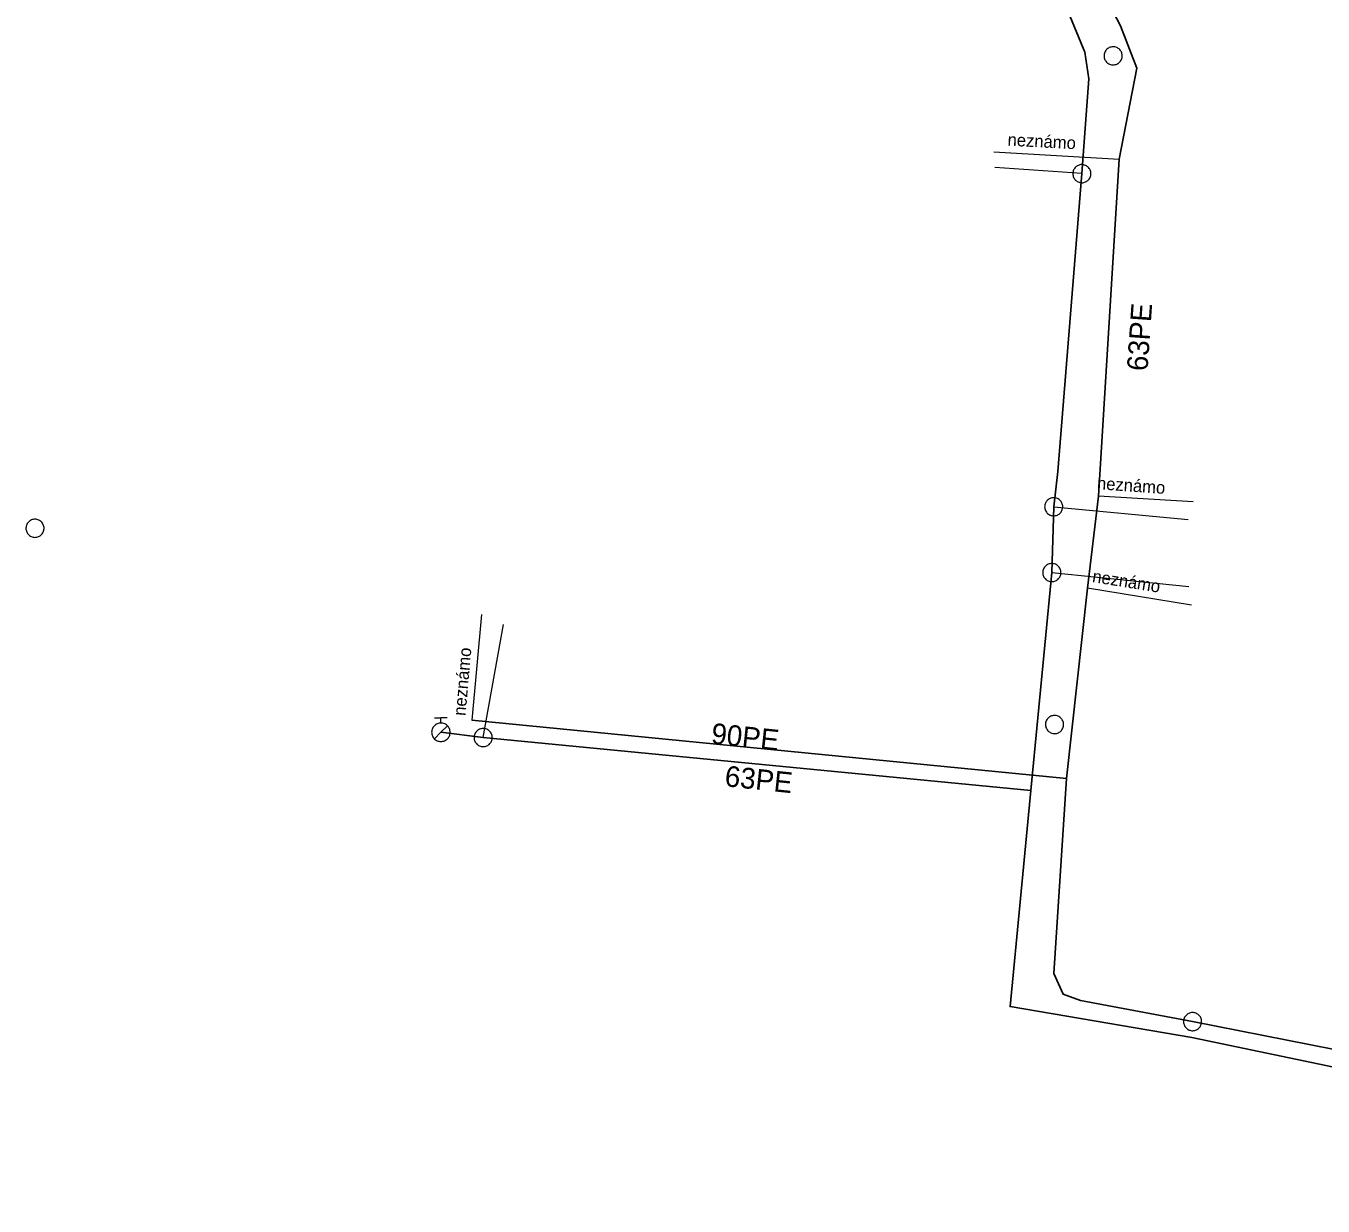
# Model space of a CAD drawing. Extents: x -741806 to -738704, y -1059275 to -1055387.
# Drawn here: x -740718.4 to -740655.8, y -1057566.4 to -1057509.4 of the extents above; entities that cross this region are included whole.
import ezdxf

# ---------------------------------------------------------------- set-up
doc = ezdxf.new("R2010")
doc.units = 0
doc.header["$LTSCALE"] = 0.4
for name, color, linetype, lineweight in [('2', 7, 'Continuous', 25), ('21', 7, 'Continuous', 13), ('3', 7, 'Continuous', 13), ('50', 7, 'Continuous', 13), ('51', 7, 'Continuous', 13), ('52', 7, 'Continuous', 25), ('56', 7, 'Continuous', 13)]:
    doc.layers.add(name, color=color, linetype=linetype, lineweight=lineweight)
for name, color, linetype in [('5', 7, 'Continuous'), ('53', 7, 'Continuous'), ('55', 7, 'Continuous')]:
    doc.layers.add(name, color=color, linetype=linetype)

msp = doc.modelspace()

# ---------------------------------------------------------------- linework, layer by layer
at = {"layer": '2'}
msp.add_line((-740696.899, -1057542.97), (-740668.18, -1057545.78), dxfattribs=at)
msp.add_lwpolyline([(-740701.18, -1057473.159), (-740698.129, -1057473.58), (-740689.684, -1057473.824), (-740686.82, -1057473.879), (-740685.879, -1057474.169), (-740685.34, -1057475.12), (-740682.62, -1057479.69), (-740667.039, -1057506.61), (-740665.579, -1057509.429), (-740664.78, -1057511.48), (-740665.629, -1057515.87), (-740666.629, -1057532.149), (-740667.16, -1057536.6), (-740668.18, -1057545.78), (-740668.8, -1057555.2), (-740668.35, -1057556.21), (-740667.51, -1057556.51), (-740662.09, -1057557.53), (-740650.66, -1057559.78), (-740647.78, -1057560.7), (-740633.18, -1057564.139), (-740633.142, -1057565.869)], dxfattribs=at)
at = {"layer": '21'}
for p, q in [((-740667.44, -1057516.57), (-740671.64, -1057516.27)), ((-740668.8, -1057532.659), (-740662.309, -1057533.27)), ((-740668.89, -1057535.84), (-740662.27, -1057536.51)), ((-740696.359, -1057543.81), (-740695.379, -1057538.35))]:
    msp.add_line(p, q, dxfattribs=at)
at = {"layer": '3'}
for points in [[(-740665.891, -1057510.442), (-740665.936, -1057510.441), (-740665.981, -1057510.444), (-740666.027, -1057510.452), (-740666.07, -1057510.465), (-740666.113, -1057510.482), (-740666.154, -1057510.503), (-740666.192, -1057510.529), (-740666.227, -1057510.558), (-740666.258, -1057510.592), (-740666.286, -1057510.627), (-740666.311, -1057510.666), (-740666.332, -1057510.708), (-740666.346, -1057510.751), (-740666.358, -1057510.795), (-740666.364, -1057510.84), (-740666.366, -1057510.886), (-740666.362, -1057510.932), (-740666.355, -1057510.977), (-740666.342, -1057511.021), (-740666.325, -1057511.064), (-740666.303, -1057511.104), (-740666.278, -1057511.141), (-740666.248, -1057511.177), (-740666.216, -1057511.209), (-740666.179, -1057511.237), (-740666.14, -1057511.261), (-740666.1, -1057511.281), (-740666.056, -1057511.297), (-740666.012, -1057511.308), (-740665.966, -1057511.314), (-740665.921, -1057511.316), (-740665.876, -1057511.313), (-740665.83, -1057511.305), (-740665.786, -1057511.292), (-740665.744, -1057511.275), (-740665.703, -1057511.254), (-740665.665, -1057511.228), (-740665.63, -1057511.198), (-740665.599, -1057511.165), (-740665.571, -1057511.13), (-740665.546, -1057511.091), (-740665.525, -1057511.049), (-740665.51, -1057511.007), (-740665.499, -1057510.962), (-740665.493, -1057510.917), (-740665.491, -1057510.871), (-740665.494, -1057510.825), (-740665.502, -1057510.78), (-740665.515, -1057510.736), (-740665.532, -1057510.693), (-740665.554, -1057510.653), (-740665.579, -1057510.615), (-740665.609, -1057510.58), (-740665.641, -1057510.548), (-740665.678, -1057510.52), (-740665.717, -1057510.496), (-740665.757, -1057510.476), (-740665.801, -1057510.46), (-740665.845, -1057510.449), (-740665.89, -1057510.442)], [(-740717.958, -1057533.265), (-740718.003, -1057533.262), (-740718.048, -1057533.264), (-740718.094, -1057533.271), (-740718.138, -1057533.282), (-740718.181, -1057533.298), (-740718.223, -1057533.318), (-740718.261, -1057533.343), (-740718.297, -1057533.37), (-740718.329, -1057533.403), (-740718.359, -1057533.438), (-740718.384, -1057533.476), (-740718.406, -1057533.517), (-740718.422, -1057533.559), (-740718.436, -1057533.603), (-740718.443, -1057533.648), (-740718.446, -1057533.694), (-740718.444, -1057533.74), (-740718.438, -1057533.785), (-740718.426, -1057533.83), (-740718.41, -1057533.873), (-740718.39, -1057533.913), (-740718.366, -1057533.951), (-740718.337, -1057533.988), (-740718.306, -1057534.021), (-740718.27, -1057534.05), (-740718.232, -1057534.075), (-740718.192, -1057534.097), (-740718.149, -1057534.114), (-740718.105, -1057534.126), (-740718.059, -1057534.134), (-740718.014, -1057534.137), (-740717.969, -1057534.135), (-740717.923, -1057534.129), (-740717.878, -1057534.117), (-740717.836, -1057534.102), (-740717.794, -1057534.081), (-740717.756, -1057534.057), (-740717.719, -1057534.028), (-740717.688, -1057533.996), (-740717.658, -1057533.961), (-740717.633, -1057533.923), (-740717.611, -1057533.883), (-740717.594, -1057533.84), (-740717.581, -1057533.796), (-740717.574, -1057533.751), (-740717.571, -1057533.705), (-740717.572, -1057533.659), (-740717.579, -1057533.614), (-740717.591, -1057533.57), (-740717.607, -1057533.526), (-740717.627, -1057533.486), (-740717.651, -1057533.447), (-740717.68, -1057533.411), (-740717.711, -1057533.378), (-740717.747, -1057533.349), (-740717.785, -1057533.323), (-740717.825, -1057533.302), (-740717.868, -1057533.285), (-740717.912, -1057533.273), (-740717.957, -1057533.265)], [(-740668.721, -1057542.742), (-740668.766, -1057542.741), (-740668.811, -1057542.744), (-740668.857, -1057542.752), (-740668.9, -1057542.765), (-740668.943, -1057542.782), (-740668.984, -1057542.803), (-740669.022, -1057542.829), (-740669.057, -1057542.858), (-740669.088, -1057542.892), (-740669.116, -1057542.927), (-740669.141, -1057542.966), (-740669.162, -1057543.008), (-740669.176, -1057543.051), (-740669.188, -1057543.095), (-740669.194, -1057543.14), (-740669.196, -1057543.186), (-740669.192, -1057543.232), (-740669.185, -1057543.277), (-740669.172, -1057543.321), (-740669.155, -1057543.364), (-740669.133, -1057543.404), (-740669.108, -1057543.441), (-740669.078, -1057543.477), (-740669.046, -1057543.509), (-740669.009, -1057543.537), (-740668.97, -1057543.561), (-740668.93, -1057543.581), (-740668.886, -1057543.597), (-740668.842, -1057543.608), (-740668.796, -1057543.614), (-740668.751, -1057543.616), (-740668.706, -1057543.613), (-740668.66, -1057543.605), (-740668.616, -1057543.592), (-740668.574, -1057543.575), (-740668.533, -1057543.554), (-740668.495, -1057543.528), (-740668.46, -1057543.498), (-740668.429, -1057543.465), (-740668.401, -1057543.43), (-740668.376, -1057543.391), (-740668.355, -1057543.349), (-740668.34, -1057543.307), (-740668.329, -1057543.262), (-740668.323, -1057543.217), (-740668.321, -1057543.171), (-740668.324, -1057543.125), (-740668.332, -1057543.08), (-740668.345, -1057543.036), (-740668.362, -1057542.993), (-740668.384, -1057542.953), (-740668.409, -1057542.915), (-740668.439, -1057542.88), (-740668.471, -1057542.848), (-740668.508, -1057542.82), (-740668.547, -1057542.796), (-740668.587, -1057542.776), (-740668.631, -1057542.76), (-740668.675, -1057542.749), (-740668.72, -1057542.742)], [(-740661.659, -1057557.611), (-740661.654, -1057557.566), (-740661.652, -1057557.521), (-740661.656, -1057557.474), (-740661.664, -1057557.43), (-740661.677, -1057557.386), (-740661.694, -1057557.343), (-740661.716, -1057557.303), (-740661.742, -1057557.265), (-740661.772, -1057557.231), (-740661.804, -1057557.199), (-740661.841, -1057557.171), (-740661.88, -1057557.146), (-740661.921, -1057557.127), (-740661.964, -1057557.111), (-740662.009, -1057557.101), (-740662.054, -1057557.094), (-740662.1, -1057557.094), (-740662.145, -1057557.096), (-740662.191, -1057557.105), (-740662.235, -1057557.118), (-740662.277, -1057557.136), (-740662.316, -1057557.157), (-740662.355, -1057557.183), (-740662.39, -1057557.212), (-740662.422, -1057557.246), (-740662.449, -1057557.282), (-740662.473, -1057557.32), (-740662.494, -1057557.362), (-740662.509, -1057557.405), (-740662.519, -1057557.45), (-740662.526, -1057557.495), (-740662.527, -1057557.54), (-740662.524, -1057557.587), (-740662.515, -1057557.632), (-740662.503, -1057557.675), (-740662.485, -1057557.718), (-740662.463, -1057557.758), (-740662.437, -1057557.796), (-740662.408, -1057557.83), (-740662.375, -1057557.862), (-740662.338, -1057557.89), (-740662.299, -1057557.915), (-740662.258, -1057557.935), (-740662.215, -1057557.95), (-740662.171, -1057557.96), (-740662.125, -1057557.967), (-740662.08, -1057557.968), (-740662.034, -1057557.965), (-740661.989, -1057557.956), (-740661.944, -1057557.943), (-740661.902, -1057557.925), (-740661.862, -1057557.905), (-740661.824, -1057557.878), (-740661.789, -1057557.849), (-740661.758, -1057557.815), (-740661.729, -1057557.779), (-740661.706, -1057557.741), (-740661.686, -1057557.699), (-740661.671, -1057557.656), (-740661.659, -1057557.612)]]:
    msp.add_lwpolyline(points, dxfattribs=at)
at = {"layer": '50'}
for p, q in [((-740698.707, -1057542.856), (-740698.399, -1057542.856)), ((-740698.399, -1057543.107), (-740698.399, -1057542.856)), ((-740698.092, -1057542.856), (-740698.399, -1057542.856)), ((-740698.399, -1057543.554), (-740698.083, -1057543.242)), ((-740698.399, -1057543.554), (-740698.716, -1057543.871))]:
    msp.add_line(p, q, dxfattribs=at)
msp.add_lwpolyline([(-740697.955, -1057543.558), (-740697.957, -1057543.509), (-740697.962, -1057543.463), (-740697.975, -1057543.417), (-740697.992, -1057543.374), (-740698.011, -1057543.334), (-740698.038, -1057543.293), (-740698.067, -1057543.258), (-740698.1, -1057543.223), (-740698.135, -1057543.193), (-740698.175, -1057543.169), (-740698.216, -1057543.147), (-740698.259, -1057543.128), (-740698.305, -1057543.118), (-740698.351, -1057543.11), (-740698.397, -1057543.107), (-740698.443, -1057543.11), (-740698.488, -1057543.115), (-740698.534, -1057543.128), (-740698.578, -1057543.145), (-740698.621, -1057543.166), (-740698.659, -1057543.191), (-740698.696, -1057543.22), (-740698.729, -1057543.253), (-740698.758, -1057543.288), (-740698.785, -1057543.328), (-740698.807, -1057543.369), (-740698.823, -1057543.412), (-740698.837, -1057543.458), (-740698.842, -1057543.504), (-740698.848, -1057543.55), (-740698.846, -1057543.598), (-740698.838, -1057543.644), (-740698.827, -1057543.687), (-740698.811, -1057543.733), (-740698.789, -1057543.774), (-740698.765, -1057543.814), (-740698.735, -1057543.849), (-740698.703, -1057543.884), (-740698.665, -1057543.914), (-740698.627, -1057543.938), (-740698.584, -1057543.96), (-740698.541, -1057543.976), (-740698.498, -1057543.99), (-740698.449, -1057543.998), (-740698.403, -1057544.001), (-740698.357, -1057543.998), (-740698.311, -1057543.99), (-740698.265, -1057543.979), (-740698.222, -1057543.963), (-740698.179, -1057543.941), (-740698.141, -1057543.917), (-740698.103, -1057543.887), (-740698.071, -1057543.855), (-740698.041, -1057543.82), (-740698.017, -1057543.779), (-740697.993, -1057543.739), (-740697.976, -1057543.695), (-740697.966, -1057543.65), (-740697.958, -1057543.604)], close=True, dxfattribs=at)
at = {"layer": '51'}
for points in [[(-740667.002, -1057516.57), (-740667.004, -1057516.525), (-740667.012, -1057516.48), (-740667.024, -1057516.435), (-740667.039, -1057516.393), (-740667.061, -1057516.352), (-740667.085, -1057516.313), (-740667.115, -1057516.278), (-740667.147, -1057516.245), (-740667.183, -1057516.217), (-740667.22, -1057516.192), (-740667.262, -1057516.171), (-740667.304, -1057516.154), (-740667.348, -1057516.142), (-740667.394, -1057516.135), (-740667.44, -1057516.133), (-740667.485, -1057516.135), (-740667.531, -1057516.142), (-740667.575, -1057516.154), (-740667.617, -1057516.171), (-740667.659, -1057516.192), (-740667.696, -1057516.217), (-740667.732, -1057516.245), (-740667.764, -1057516.278), (-740667.794, -1057516.313), (-740667.818, -1057516.352), (-740667.84, -1057516.393), (-740667.855, -1057516.435), (-740667.867, -1057516.48), (-740667.875, -1057516.525), (-740667.877, -1057516.571), (-740667.875, -1057516.616), (-740667.867, -1057516.661), (-740667.855, -1057516.706), (-740667.84, -1057516.748), (-740667.818, -1057516.789), (-740667.794, -1057516.828), (-740667.764, -1057516.863), (-740667.732, -1057516.896), (-740667.696, -1057516.924), (-740667.659, -1057516.949), (-740667.617, -1057516.97), (-740667.575, -1057516.987), (-740667.531, -1057516.998), (-740667.485, -1057517.006), (-740667.44, -1057517.008), (-740667.394, -1057517.006), (-740667.348, -1057516.998), (-740667.304, -1057516.987), (-740667.262, -1057516.97), (-740667.22, -1057516.949), (-740667.183, -1057516.924), (-740667.147, -1057516.896), (-740667.115, -1057516.863), (-740667.085, -1057516.828), (-740667.061, -1057516.789), (-740667.039, -1057516.748), (-740667.024, -1057516.706), (-740667.012, -1057516.661), (-740667.004, -1057516.616), (-740667.002, -1057516.571)], [(-740668.363, -1057532.659), (-740668.365, -1057532.614), (-740668.372, -1057532.569), (-740668.384, -1057532.524), (-740668.4, -1057532.482), (-740668.421, -1057532.441), (-740668.446, -1057532.402), (-740668.475, -1057532.367), (-740668.507, -1057532.334), (-740668.543, -1057532.306), (-740668.581, -1057532.281), (-740668.622, -1057532.26), (-740668.665, -1057532.243), (-740668.709, -1057532.231), (-740668.754, -1057532.224), (-740668.8, -1057532.222), (-740668.846, -1057532.224), (-740668.891, -1057532.231), (-740668.935, -1057532.243), (-740668.978, -1057532.26), (-740669.019, -1057532.281), (-740669.057, -1057532.306), (-740669.093, -1057532.334), (-740669.125, -1057532.367), (-740669.154, -1057532.402), (-740669.179, -1057532.441), (-740669.2, -1057532.482), (-740669.216, -1057532.524), (-740669.228, -1057532.569), (-740669.235, -1057532.614), (-740669.238, -1057532.66), (-740669.235, -1057532.705), (-740669.228, -1057532.75), (-740669.216, -1057532.795), (-740669.2, -1057532.837), (-740669.179, -1057532.878), (-740669.154, -1057532.917), (-740669.125, -1057532.952), (-740669.093, -1057532.985), (-740669.057, -1057533.013), (-740669.019, -1057533.038), (-740668.978, -1057533.059), (-740668.935, -1057533.076), (-740668.891, -1057533.087), (-740668.846, -1057533.095), (-740668.8, -1057533.097), (-740668.754, -1057533.095), (-740668.709, -1057533.087), (-740668.665, -1057533.076), (-740668.622, -1057533.059), (-740668.581, -1057533.038), (-740668.543, -1057533.013), (-740668.507, -1057532.985), (-740668.475, -1057532.952), (-740668.446, -1057532.917), (-740668.421, -1057532.878), (-740668.4, -1057532.837), (-740668.384, -1057532.795), (-740668.372, -1057532.75), (-740668.365, -1057532.705), (-740668.363, -1057532.66)], [(-740668.453, -1057535.84), (-740668.455, -1057535.795), (-740668.462, -1057535.75), (-740668.474, -1057535.705), (-740668.49, -1057535.663), (-740668.511, -1057535.622), (-740668.536, -1057535.583), (-740668.565, -1057535.548), (-740668.597, -1057535.515), (-740668.633, -1057535.487), (-740668.671, -1057535.462), (-740668.712, -1057535.441), (-740668.755, -1057535.424), (-740668.799, -1057535.412), (-740668.844, -1057535.405), (-740668.89, -1057535.403), (-740668.936, -1057535.405), (-740668.981, -1057535.412), (-740669.025, -1057535.424), (-740669.068, -1057535.441), (-740669.109, -1057535.462), (-740669.147, -1057535.487), (-740669.183, -1057535.515), (-740669.215, -1057535.548), (-740669.244, -1057535.583), (-740669.269, -1057535.622), (-740669.29, -1057535.663), (-740669.306, -1057535.705), (-740669.318, -1057535.75), (-740669.325, -1057535.795), (-740669.328, -1057535.841), (-740669.325, -1057535.886), (-740669.318, -1057535.931), (-740669.306, -1057535.976), (-740669.29, -1057536.018), (-740669.269, -1057536.059), (-740669.244, -1057536.098), (-740669.215, -1057536.133), (-740669.183, -1057536.166), (-740669.147, -1057536.194), (-740669.109, -1057536.219), (-740669.068, -1057536.24), (-740669.025, -1057536.257), (-740668.981, -1057536.268), (-740668.936, -1057536.276), (-740668.89, -1057536.278), (-740668.844, -1057536.276), (-740668.799, -1057536.268), (-740668.755, -1057536.257), (-740668.712, -1057536.24), (-740668.671, -1057536.219), (-740668.633, -1057536.194), (-740668.597, -1057536.166), (-740668.565, -1057536.133), (-740668.536, -1057536.098), (-740668.511, -1057536.059), (-740668.49, -1057536.018), (-740668.474, -1057535.976), (-740668.462, -1057535.931), (-740668.455, -1057535.886), (-740668.453, -1057535.841)], [(-740695.922, -1057543.81), (-740695.924, -1057543.765), (-740695.931, -1057543.72), (-740695.943, -1057543.675), (-740695.959, -1057543.633), (-740695.98, -1057543.592), (-740696.005, -1057543.553), (-740696.034, -1057543.518), (-740696.066, -1057543.485), (-740696.102, -1057543.457), (-740696.14, -1057543.432), (-740696.181, -1057543.411), (-740696.224, -1057543.394), (-740696.268, -1057543.382), (-740696.313, -1057543.375), (-740696.359, -1057543.373), (-740696.405, -1057543.375), (-740696.45, -1057543.382), (-740696.494, -1057543.394), (-740696.537, -1057543.411), (-740696.578, -1057543.432), (-740696.616, -1057543.457), (-740696.652, -1057543.485), (-740696.684, -1057543.518), (-740696.713, -1057543.553), (-740696.738, -1057543.592), (-740696.759, -1057543.633), (-740696.775, -1057543.675), (-740696.787, -1057543.72), (-740696.794, -1057543.765), (-740696.797, -1057543.811), (-740696.794, -1057543.856), (-740696.787, -1057543.901), (-740696.775, -1057543.946), (-740696.759, -1057543.988), (-740696.738, -1057544.029), (-740696.713, -1057544.068), (-740696.684, -1057544.103), (-740696.652, -1057544.136), (-740696.616, -1057544.164), (-740696.578, -1057544.189), (-740696.537, -1057544.21), (-740696.494, -1057544.227), (-740696.45, -1057544.238), (-740696.405, -1057544.246), (-740696.359, -1057544.248), (-740696.313, -1057544.246), (-740696.268, -1057544.238), (-740696.224, -1057544.227), (-740696.181, -1057544.21), (-740696.14, -1057544.189), (-740696.102, -1057544.164), (-740696.066, -1057544.136), (-740696.034, -1057544.103), (-740696.005, -1057544.068), (-740695.98, -1057544.029), (-740695.959, -1057543.988), (-740695.943, -1057543.946), (-740695.931, -1057543.901), (-740695.924, -1057543.856), (-740695.922, -1057543.811)]]:
    msp.add_lwpolyline(points, dxfattribs=at)
at = {"layer": '52'}
for points in [[(-740669.903, -1057546.362), (-740668.89, -1057535.84), (-740668.8, -1057532.659), (-740668.6, -1057530.96), (-740667.44, -1057516.57), (-740667.109, -1057511.99), (-740667.289, -1057510.7), (-740668.399, -1057507.99), (-740683.739, -1057481.02), (-740686.96, -1057476.45), (-740689.02, -1057475.889), (-740697.39, -1057475.629), (-740700.809, -1057475.34), (-740703.14, -1057474.73)], [(-740669.903, -1057546.362), (-740696.359, -1057543.81), (-740698.399, -1057543.55)], [(-740622.261, -1057566.439), (-740622.739, -1057566.399), (-740633.96, -1057565.02), (-740651.25, -1057560.57), (-740662.129, -1057558.3), (-740670.91, -1057556.8), (-740669.903, -1057546.362)]]:
    msp.add_lwpolyline(points, dxfattribs=at)
at = {"layer": '56'}
for p, q in [((-740671.699, -1057515.51), (-740665.629, -1057515.87)), ((-740662.07, -1057532.429), (-740666.629, -1057532.149)), ((-740662.14, -1057537.419), (-740667.16, -1057536.6)), ((-740696.44, -1057537.86), (-740696.899, -1057542.97))]:
    msp.add_line(p, q, dxfattribs=at)

# ---------------------------------------------------------------- texts
at = {"layer": '5'}
for rotation, p in [(86, (-740664.27, -1057526.127)), (354, (-740684.723, -1057546.155))]:
    msp.add_text('63PE', height=1, rotation=rotation, dxfattribs=at).set_placement(p)
at = {"layer": '53'}
msp.add_text('90PE', height=1, rotation=354, dxfattribs=at).set_placement((-740685.375, -1057544.096))
at = {"layer": '55'}
for rotation, p in [(357, (-740671.04, -1057515.217)), (356, (-740666.724, -1057531.812)), (351, (-740666.964, -1057536.296)), (85, (-740697.214, -1057542.775))]:
    msp.add_text('neznámo ', height=0.6, rotation=rotation, dxfattribs=at).set_placement(p)

doc.saveas('drawing.dxf')
